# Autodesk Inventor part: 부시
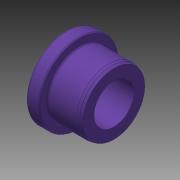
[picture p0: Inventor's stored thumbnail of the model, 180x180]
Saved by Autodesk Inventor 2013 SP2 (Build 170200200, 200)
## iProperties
Created: 2016-05
Part Number: 부시
Document SubType Name: Modeling
Designer: mduedu
Density: 7.86 g/cm^3
Material: 강철, 연강
Author: mduedu
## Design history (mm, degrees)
sketch "스케치1"
  geometry: L1 (0, 0)-(18, 0); L2 (1.5, 7.5)-(18, 7.5); L3 (18, 7.5)-(18, 11.598); L4 (16.5, 12)-(5, 12); L5 (5, 12)-(5, 15); L6 (5, 15)-(0, 15); L7 (0, 15)-(0, 7.902); L8 (0, 7.902)-(1.5, 7.5); L9 (16.5, 12)-(18, 11.598)
  constraints: 18 end point, 4 parallel, 1 horizontal, 1 perpendicular, 1 point on line, 1 vertical, 1 vertical alignment
  dimensions: "d0" = 18 distance of L1.start L1.end; "d1" = 15 diameter of L2 L1; "d2" = 24 diameter of L4 L1; "d3" = 5 distance of L5.end L6.end; "d4" = 30 diameter of L6 L1; "d9" = 15 deg angle of L2 L8; "d10" = 1.5 horizontal distance of L7.end L2.start; "d13" = 15 deg angle of L4 L9; "d14" = 1.5 distance from line of L4.start L3
revolve "회전1" sketch "스케치1" stored, may be unused: angle "d5" = 90 deg
fillet "모깎기1" dims "d11" = 4
fillet "모깎기2" dims "d12" = 0.5
node "솔리드1"
